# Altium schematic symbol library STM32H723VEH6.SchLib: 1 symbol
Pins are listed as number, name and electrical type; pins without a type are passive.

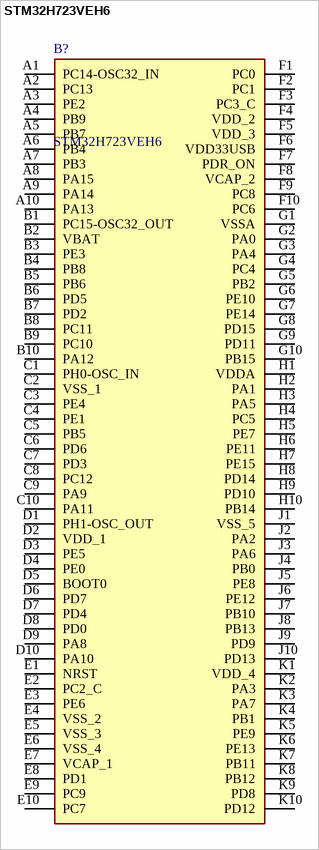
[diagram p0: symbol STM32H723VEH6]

## STM32H723VEH6
designator B?
High-performance and DSP with DP-FPU, Arm Cortex-M7 MCU with 512 Kbytes Flash, 564 Kbytes RAM, 550 MHz CPU, L1 cache, external memory interface, subset of peripherals; Manufacturer_Name: STMicroelectronics; Geometry.Height: 1.1mm
footprint BGA100C80P10X10_800X800X110
pins: A1 PC14-OSC32_IN, A2 PC13, A3 PE2, A4 PB9, A5 PB7, A6 PB4, A7 PB3, A8 PA15, A9 PA14, A10 PA13, B1 PC15-OSC32_OUT, B2 VBAT, B3 PE3, B4 PB8, B5 PB6, B6 PD5, B7 PD2, B8 PC11, B9 PC10, B10 PA12, C1 PH0-OSC_IN, C2 VSS_1, C3 PE4, C4 PE1, C5 PB5, C6 PD6, C7 PD3, C8 PC12, C9 PA9, C10 PA11, D1 PH1-OSC_OUT, D2 VDD_1, D3 PE5, D4 PE0, D5 BOOT0, D6 PD7, D7 PD4, D8 PD0, D9 PA8, D10 PA10, E1 NRST, E2 PC2_C, E3 PE6, E4 VSS_2, E5 VSS_3, E6 VSS_4, E7 VCAP_1, E8 PD1, E9 PC9, E10 PC7, F1 PC0, F2 PC1, F3 PC3_C, F4 VDD_2, F5 VDD_3, F6 VDD33USB, F7 PDR_ON, F8 VCAP_2, F9 PC8, F10 PC6, G1 VSSA, G2 PA0, G3 PA4, G4 PC4, G5 PB2, G6 PE10, G7 PE14, G8 PD15, G9 PD11, G10 PB15, H1 VDDA, H2 PA1, H3 PA5, H4 PC5, H5 PE7, H6 PE11, H7 PE15, H8 PD14, H9 PD10, H10 PB14, J1 VSS_5, J2 PA2, J3 PA6, J4 PB0, J5 PE8, J6 PE12, J7 PB10, J8 PB13, J9 PD9, J10 PD13, K1 VDD_4, K2 PA3, K3 PA7, K4 PB1, K5 PE9, K6 PE13, K7 PB11, K8 PB12, K9 PD8, K10 PD12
